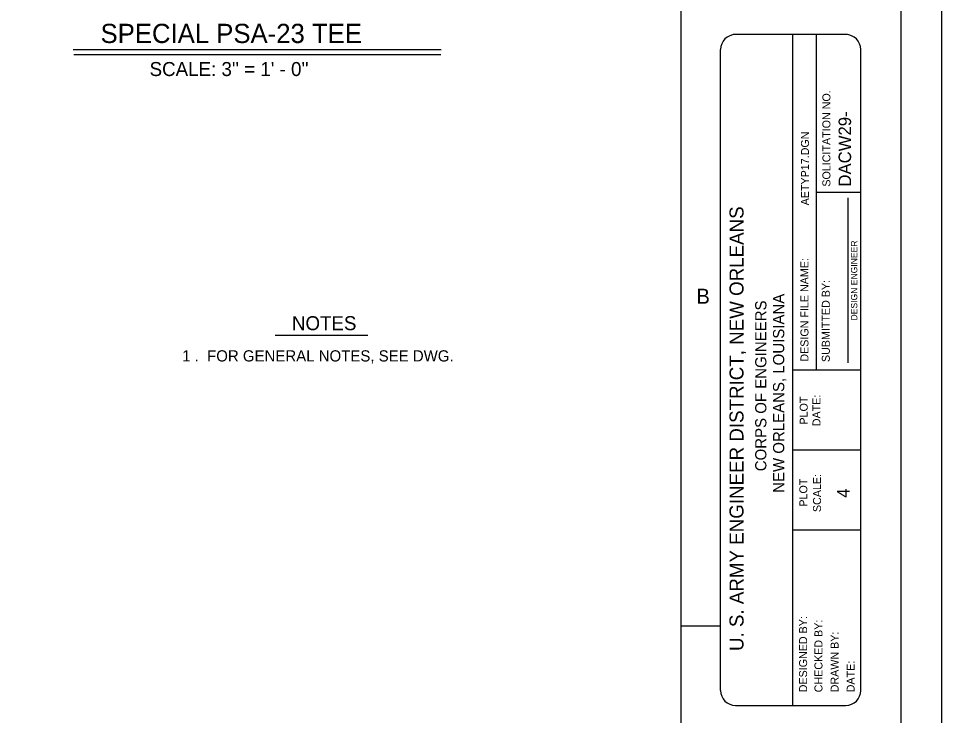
# Model space of a CAD drawing. Extents: x 22369.6 to 22384.3, y 22369.6 to 22381.8.
# Drawn here: x 22380.446 to 22384.288, y 22372.163 to 22375.064 of the extents above; entities that cross this region are included whole.
import ezdxf

# ---------------------------------------------------------------- set-up
doc = ezdxf.new("R2010")
doc.units = 0
for name, color, linetype in [('Level 1', 7, 'Continuous'), ('Level 10', 7, 'Continuous'), ('Level 2', 7, 'Continuous'), ('Level 3', 7, 'Continuous'), ('Level 4', 7, 'Continuous'), ('Level 7', 7, 'Continuous'), ('Level 9', 7, 'Continuous')]:
    doc.layers.add(name, color=color, linetype=linetype)

msp = doc.modelspace()

# ---------------------------------------------------------------- linework, layer by layer
at = {"layer": 'Level 1'}
for p, q in [((22383.8961, 22374.9973), (22383.4201, 22374.9973)), ((22383.6681, 22374.9973), (22383.6681, 22372.2053))]:
    msp.add_line(p, q, dxfattribs=at)
msp.add_lwpolyline([(22369.6213, 22380.9573), (22384.2881, 22380.9573), (22384.2881, 22369.6213), (22369.6213, 22369.6213)], close=True, dxfattribs=at)
for points in [[(22383.8896, 22374.9973), (22383.4306, 22374.9973)], [(22383.3681, 22372.2678), (22383.3681, 22374.9348)], [(22383.9521, 22372.2678), (22383.9521, 22374.9348)], [(22383.4306, 22372.2053), (22383.8896, 22372.2053)]]:
    msp.add_lwpolyline(points, dxfattribs=at)
for centre, start, end in [((22383.4306, 22374.9348), 90, 180), ((22383.8896, 22374.9348), 0, 90), ((22383.4306, 22372.2678), 180, 270), ((22383.8896, 22372.2678), 270, 0)]:
    msp.add_arc(centre, 0.0625, start, end, dxfattribs=at)
at = {"layer": 'Level 10'}
for p, q in [((22380.6732, 22374.9354), (22382.2052, 22374.9354)), ((22380.6758, 22374.9145), (22382.2033, 22374.9145)), ((22383.2041, 22372.5373), (22383.3681, 22372.5373))]:
    msp.add_line(p, q, dxfattribs=at)
at = {"layer": 'Level 2'}
for p, q in [((22383.7664, 22374.9973), (22383.7664, 22373.6013)), ((22383.9521, 22374.3401), (22383.7664, 22374.3401)), ((22383.9001, 22373.6316), (22383.9001, 22374.3186)), ((22383.9521, 22373.6013), (22383.6681, 22373.6013)), ((22383.9521, 22373.268), (22383.6681, 22373.268)), ((22383.9521, 22372.9346), (22383.6681, 22372.9346))]:
    msp.add_line(p, q, dxfattribs=at)
at = {"layer": 'Level 7'}
msp.add_line((22381.5141, 22373.7461), (22381.8997, 22373.7461), dxfattribs=at)
at = {"layer": 'Level 9'}
msp.add_line((22384.1201, 22369.7893), (22384.1201, 22380.7893), dxfattribs=at)
msp.add_lwpolyline([(22383.2041, 22369.7893), (22383.2041, 22380.7893)], dxfattribs=at)

# ---------------------------------------------------------------- texts
at = {"layer": 'Level 1'}
for s, height, p in [('SOLICITATION NO.', 0.033336, (22383.8255, 22374.3644)), ('AETYP17.DGN', 0.033333, (22383.7363, 22374.2867)), ('U. S. ARMY ENGINEER DISTRICT, NEW ORLEANS', 0.058333, (22383.4638, 22372.4318)), ('DESIGN ENGINEER', 0.026664, (22383.9376, 22373.8075)), ('DESIGN FILE NAME:', 0.033336, (22383.7341, 22373.6361)), ('SUBMITTED BY:', 0.033336, (22383.823, 22373.6344)), ('PLOT', 0.03334, (22383.731, 22373.3743)), ('DATE:', 0.03334, (22383.7842, 22373.3674)), ('SCALE:', 0.03334, (22383.7865, 22373.0101)), ('PLOT', 0.03334, (22383.7294, 22373.0327)), ('DESIGNED BY:', 0.033336, (22383.7284, 22372.2599)), ('CHECKED BY:', 0.033336, (22383.7924, 22372.2599)), ('DRAWN BY:', 0.03334, (22383.8597, 22372.2599)), ('DATE:', 0.03334, (22383.9263, 22372.2599))]:
    msp.add_text(s, height=height, rotation=90, dxfattribs=at).set_placement(p)
msp.add_text('B', height=0.0624, dxfattribs=at).set_placement((22383.2681, 22373.8773))
at = {"layer": 'Level 3'}
msp.add_text('SPECIAL PSA-23 TEE', height=0.08, dxfattribs=at).set_placement((22380.7873, 22374.9622))
at = {"layer": 'Level 4'}
for s, height, p in [("SCALE: 3'' = 1' - 0''", 0.058333, (22380.9914, 22374.8248)), ('NOTES', 0.0583, (22381.5839, 22373.7671)), ('1 .  FOR GENERAL NOTES, SEE DWG.', 0.046667, (22381.1267, 22373.6368))]:
    msp.add_text(s, height=height, dxfattribs=at).set_placement(p)
at = {"layer": 'Level 7'}
for s, height, p in [('DACW29-', 0.052, (22383.9116, 22374.3648)), ('CORPS OF ENGINEERS', 0.046666, (22383.559, 22373.18)), ('NEW ORLEANS, LOUISIANA', 0.046666, (22383.6333, 22373.0901)), ('4', 0.052, (22383.9052, 22373.0693))]:
    msp.add_text(s, height=height, rotation=90, dxfattribs=at).set_placement(p)

doc.saveas('drawing.dxf')
